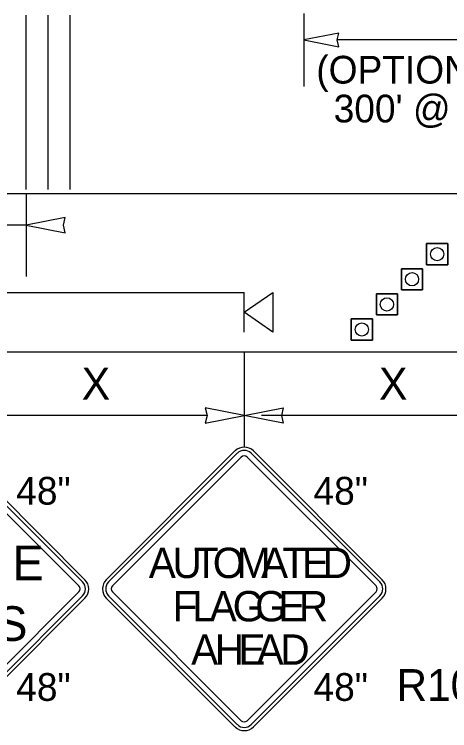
# Model space of a CAD drawing. Extents: x 99999.1 to 100095.7, y 99995 to 100010.7.
# Drawn here: x 100042.947 to 100044.045, y 100004.777 to 100006.584 of the extents above; entities that cross this region are included whole.
import ezdxf

# ---------------------------------------------------------------- set-up
doc = ezdxf.new("R2010")
doc.units = 0
for name, color, linetype in [('RD_ED_ShoulderPavedEdge', 7, 'Continuous'), ('RD_MK_LineEdgeWhite', 7, 'Continuous'), ('TR_SN_ConstructionSigns', 7, 'Continuous'), ('TR_WZ_PortableSignMountBlk-Org', 7, 'Continuous'), ('TR_WZ_TrafficCone', 7, 'Continuous'), ('TR_WZ_WorkZoneDetails', 7, 'Continuous'), ('TR_WZ_WorkZoneTextCurrent', 7, 'Continuous')]:
    doc.layers.add(name, color=color, linetype=linetype)

msp = doc.modelspace()

# ---------------------------------------------------------------- linework, layer by layer
at = {"layer": 'RD_ED_ShoulderPavedEdge'}
msp.add_line((100040.1076, 100005.7323), (100055.6424, 100005.7323), dxfattribs=at)
at = {"layer": 'RD_MK_LineEdgeWhite'}
msp.add_line((100040.1076, 100006.1323), (100055.6424, 100006.1323), dxfattribs=at)
at = {"layer": 'TR_SN_ConstructionSigns'}
for p, q in [((100043.1247, 100005.1579), (100042.7999, 100005.4827)), ((100043.5034, 100005.4827), (100043.1786, 100005.1579)), ((100043.8747, 100005.1579), (100043.5499, 100005.4827)), ((100042.7844, 100005.4673), (100043.1092, 100005.1424)), ((100043.1189, 100005.1521), (100042.7941, 100005.4769)), ((100043.5092, 100005.4769), (100043.1844, 100005.1521)), ((100043.1941, 100005.1424), (100043.5189, 100005.4673)), ((100043.5344, 100005.4673), (100043.8592, 100005.1424)), ((100043.8689, 100005.1521), (100043.5441, 100005.4769)), ((100043.1092, 100005.127), (100042.7844, 100004.8021)), ((100043.5189, 100004.8021), (100043.1941, 100005.127)), ((100043.8592, 100005.127), (100043.5344, 100004.8021)), ((100042.7941, 100004.7925), (100043.1189, 100005.1173)), ((100042.7999, 100004.7867), (100043.1247, 100005.1115)), ((100043.1786, 100005.1115), (100043.5034, 100004.7867)), ((100043.1844, 100005.1173), (100043.5092, 100004.7925)), ((100043.5441, 100004.7925), (100043.8689, 100005.1173)), ((100043.5499, 100004.7867), (100043.8747, 100005.1115))]:
    msp.add_line(p, q, dxfattribs=at)
for centre, radius, start, end in [((100043.5267, 100005.4595), 0.0328, 45, 135), ((100043.5267, 100005.4595), 0.0246, 45, 135), ((100043.5267, 100005.4595), 0.0109, 45, 135), ((100043.1015, 100005.1347), 0.0328, 315, 45), ((100043.2018, 100005.1347), 0.0328, 135, 225), ((100043.8515, 100005.1347), 0.0328, 315, 45), ((100043.1015, 100005.1347), 0.0109, 315, 45), ((100043.1015, 100005.1347), 0.0246, 315, 45), ((100043.2018, 100005.1347), 0.0246, 135, 225), ((100043.2018, 100005.1347), 0.0109, 135, 225), ((100043.8515, 100005.1347), 0.0109, 315, 45), ((100043.8515, 100005.1347), 0.0246, 315, 45), ((100043.5267, 100004.8099), 0.0109, 225, 315), ((100043.5267, 100004.8099), 0.0328, 225, 315), ((100043.5267, 100004.8099), 0.0246, 225, 315)]:
    msp.add_arc(centre, radius, start, end, dxfattribs=at)
at = {"layer": 'TR_WZ_PortableSignMountBlk-Org'}
msp.add_line((100043.5267, 100005.7824), (100043.5267, 100005.8824), dxfattribs=at)
msp.add_lwpolyline([(100043.5267, 100005.8323), (100043.5985, 100005.8824), (100043.5985, 100005.7824)], close=True, dxfattribs=at)
at = {"layer": 'TR_WZ_TrafficCone'}
for points in [[(100043.9867, 100006.0057), (100044.04, 100006.0057), (100044.04, 100005.9523), (100043.9867, 100005.9523), (100043.9867, 100006.0057)], [(100043.9867, 100005.9523), (100044.04, 100005.9523), (100044.04, 100006.0057), (100043.9867, 100006.0057), (100043.9867, 100005.9523)], [(100043.9767, 100005.9423), (100043.9233, 100005.9423), (100043.9233, 100005.889), (100043.9767, 100005.889), (100043.9767, 100005.9423)], [(100043.9767, 100005.889), (100043.9233, 100005.889), (100043.9233, 100005.9423), (100043.9767, 100005.9423), (100043.9767, 100005.889)], [(100043.9133, 100005.879), (100043.86, 100005.879), (100043.86, 100005.8257), (100043.9133, 100005.8257), (100043.9133, 100005.879)], [(100043.9133, 100005.8257), (100043.86, 100005.8257), (100043.86, 100005.879), (100043.9133, 100005.879), (100043.9133, 100005.8257)], [(100043.85, 100005.8157), (100043.7967, 100005.8157), (100043.7967, 100005.7623), (100043.85, 100005.7623), (100043.85, 100005.8157)], [(100043.85, 100005.7623), (100043.7967, 100005.7623), (100043.7967, 100005.8157), (100043.85, 100005.8157), (100043.85, 100005.7623)]]:
    msp.add_lwpolyline(points, dxfattribs=at)
for centre in [(100044.0133, 100005.979), (100043.95, 100005.9157), (100043.8867, 100005.8523), (100043.8233, 100005.789)]:
    msp.add_circle(centre, 0.0167, dxfattribs=at)
at = {"layer": 'TR_WZ_WorkZoneDetails'}
for p, q in [((100043.6767, 100006.5857), (100043.6767, 100006.4023)), ((100042.9767, 100006.1423), (100042.9767, 100006.5823)), ((100043.0323, 100006.1423), (100043.0323, 100006.5823)), ((100043.0872, 100006.1423), (100043.0872, 100006.5823)), ((100044.1923, 100006.5193), (100043.761, 100006.5193)), ((100042.9767, 100006.1323), (100042.9767, 100005.9223)), ((100042.9767, 100006.0523), (100042.7767, 100006.0523)), ((100040.5267, 100005.8824), (100043.5267, 100005.8824)), ((100043.5267, 100005.7323), (100043.5267, 100005.4923)), ((100043.4329, 100005.5723), (100042.8704, 100005.5723)), ((100044.1829, 100005.5723), (100043.5704, 100005.5723)), ((100044.1829, 100005.5723), (100043.6204, 100005.5723))]:
    msp.add_line(p, q, dxfattribs=at)
for points in [[(100043.6767, 100006.5193), (100043.7651, 100006.502), (100043.761, 100006.5193), (100043.7651, 100006.5367)], [(100042.9767, 100006.0523), (100043.0749, 100006.0331), (100043.0704, 100006.0523), (100043.0749, 100006.0716)], [(100043.5267, 100005.5723), (100043.4284, 100005.5916), (100043.4329, 100005.5723), (100043.4284, 100005.5531)], [(100043.5267, 100005.5723), (100043.6249, 100005.5916), (100043.6204, 100005.5723), (100043.6249, 100005.5531)]]:
    msp.add_lwpolyline(points, close=True, dxfattribs=at)

# ---------------------------------------------------------------- texts
at = {"layer": 'TR_SN_ConstructionSigns'}
for s, height, p in [('48"', 0.07, (100042.9515, 100005.3472)), ('48"', 0.07, (100043.7015, 100005.3472)), ('48"', 0.07, (100042.9515, 100004.8522)), ('48"', 0.07, (100043.7015, 100004.8522)), ('R10-6A (B/W)', 0.08, (100043.9107, 100004.8523))]:
    msp.add_text(s, height=height, rotation=360, dxfattribs=at).set_placement(p)
for s, height, p in [('E', 0.0875, (100042.9425, 100005.1566)), ('A', 0.0766, (100043.2859, 100005.162)), ('U', 0.0766, (100043.3456, 100005.162)), ('T', 0.0766, (100043.3992, 100005.162)), ('O', 0.0766, (100043.4474, 100005.162)), ('M', 0.0766, (100043.5079, 100005.162)), ('A', 0.0766, (100043.5691, 100005.162)), ('T', 0.0766, (100043.6227, 100005.162)), ('E', 0.0766, (100043.6725, 100005.162)), ('D', 0.0766, (100043.7246, 100005.162)), ('F', 0.0766, (100043.346, 100005.0527)), ('L', 0.0766, (100043.3957, 100005.0527)), ('A', 0.0766, (100043.4394, 100005.0527)), ('G', 0.0766, (100043.4976, 100005.0527)), ('G', 0.0766, (100043.5542, 100005.0527)), ('E', 0.0766, (100043.6124, 100005.0527)), ('R', 0.0766, (100043.6645, 100005.0527)), ('S', 0.0875, (100042.9018, 100005.0034)), ('A', 0.0766, (100043.3927, 100004.9433)), ('H', 0.0766, (100043.4524, 100004.9433)), ('E', 0.0766, (100043.5121, 100004.9433)), ('A', 0.0766, (100043.558, 100004.9433)), ('D', 0.0766, (100043.6178, 100004.9433))]:
    msp.add_text(s, height=height, dxfattribs=at).set_placement(p)
at = {"layer": 'TR_WZ_WorkZoneTextCurrent'}
for s, p in [('(OPTIONAL)', (100043.7085, 100006.4093)), ("300' @", (100043.7523, 100006.3113))]:
    msp.add_text(s, height=0.07, dxfattribs=at).set_placement(p)
for p in [(100043.1169, 100005.6123), (100043.8669, 100005.6123)]:
    msp.add_text('X', height=0.08, rotation=360, dxfattribs=at).set_placement(p)

doc.saveas('drawing.dxf')
